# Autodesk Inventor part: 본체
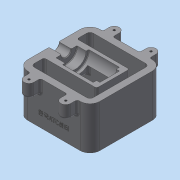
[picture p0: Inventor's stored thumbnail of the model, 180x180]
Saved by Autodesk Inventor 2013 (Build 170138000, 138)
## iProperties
Created: 2018-01
Part Number: 본체
Material: 일반
Document SubType Name: Modeling
Designer: dgall
Density: 1 g/cm^3
Author: dgall
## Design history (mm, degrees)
sketch "스케치1"
  geometry: L1 (0, 0)-(110, 0); L2 (110, 0)-(110, 110); L3 (110, 110)-(0, 110); L4 (0, 110)-(0, 0); L5 (10, 100)-(100, 100); L6 (100, 100)-(100, 10); L7 (100, 10)-(10, 10); L8 (10, 10)-(10, 100)
  constraints: 16 end point, 4 parallel, 2 perpendicular, 1 horizontal, 3 other
  dimensions: "d0" = 110 distance of L1.start L1.end; "d1" = 110 distance of L1.end L2.end; "d2" = 10 distance between parallel lines of L5 L3
extrude "돌출1" new body sketch "스케치1" distance "d3" = 65; taper "d4" = 0 deg
sketch "스케치2"
  geometry: L1 (110, 110)-(0, 110) reference; L2 (0, 110)-(0, 0) reference; L3 (19.5, 120)-(19.5, 110); L4 (34.5, 120)-(34.5, 110); L5 (75.5, 120)-(75.5, 110); L6 (90.5, 120)-(90.5, 110); A1 r 7.5 centre (27, 120) between (34.5, 120) and (19.5, 120); A2 r 7.5 centre (83, 120) between (90.5, 120) and (75.5, 120)
  constraints: 8 end point, 4 perpendicular, 4 point on circle, 4 point on line, 4 tangent, 2 centre point, 1 horizontal alignment
  dimensions: "d5" = 15 diameter of A1; "d6" = 15 diameter of A2; "d7" = 27 distance from line of A1.centre L2; "d8" = 56 distance of A2.centre A1.centre; "d9" = 10 distance from line of A1.centre L1
extrude "돌출2" join sketch "스케치2" distance "d10" = 20; taper "d11" = 0 deg
node "작업 평면1"
sketch "스케치3"
  geometry: A1 r 7.5 centre (27, -10) between (19.5, -10) and (34.5, -10) reference; A2 r 7.5 centre (83, -10) between (75.5, -10) and (90.5, -10) reference; A3 r 7.5 centre (83, 120) between (90.5, 120) and (75.5, 120) reference; A4 r 7.5 centre (27, 120) between (34.5, 120) and (19.5, 120) reference; 4 further points
  constraints: 4 coincident
hole "구멍1" sketch "스케치3" at (27, 120), (83, 120), (27, -10), (83, -10) diameter "d12" = 3.242; stored, may be unused: countersink angle "d16" = 90 deg, drill point angle "d18" = 118 deg; dims "d13" = 9, "d14" = 4, "d15" = 2, "d17" = 11
node "작업 평면2"
sketch "스케치5"
  geometry: L1 (0, 0)-(0, 65) reference; L2 (0, 65)-(10, 65) reference; L3 (10, 65)-(10, 0) reference; L4 (10, 0)-(0, 0) reference; L5 (110, 65)-(110, 0) reference; L6 (110, 0)-(100, 0) reference; L7 (100, 0)-(100, 65) reference; L8 (100, 65)-(110, 65) reference; L9 (90, 65)-(90, 30); L10 (90, 30)-(10, 8.564); L11 (10, 65)-(10, 8.564); L12 (10, 65)-(90, 65); L13 (100, 0)-(10, 0) reference
  constraints: 8 end point, 2 perpendicular, 1 parallel, 1 point on line
  dimensions: "d22" = 20 distance between parallel lines of L5 L9; "d23" = 105 deg angle of L3 L10; "d24" = 30 distance from line of L13 L9.end
extrude "돌출3" join sketch "스케치5" distance "d25" = 50; taper "d26" = 0 deg
sketch "스케치6"
  geometry: L1 (65, 110)-(65, 0) reference; C1 r 7.5 at (65, 55)
  constraints: 1 centre point, 1 midpoint
  dimensions: "d27" = 15 diameter of C1
extrude "돌출4" cut sketch "스케치6" distance "d28" = 19; taper "d29" = 0 deg
sketch "스케치7"
  geometry: C1 r 16 at (65, 55); A1 r 7.5 centre (65, 55) between (65, 62.5) and (65, 47.5) reference; 1 further point
  constraints: 1 centre point, 1 coincident
  dimensions: "d30" = 32 diameter of C1
extrude "돌출5" cut sketch "스케치7" distance "d31" = 14; taper "d32" = 0 deg
sketch "스케치8"
  geometry: C1 r 20 at (65, 55); A1 r 16 centre (65, 55) between (65, 71) and (65, 39) reference; 1 further point
  constraints: 1 centre point, 1 coincident
  dimensions: "d33" = 40 diameter of C1
extrude "돌출6" cut sketch "스케치8" distance "d34" = 47; taper "d35" = 0 deg
sketch "스케치9"
  geometry: C1 r 15 at (65, 55); A1 r 20 centre (65, 55) between (65, 75) and (65, 35) reference; 1 further point
  constraints: 1 centre point, 1 coincident
  dimensions: "d36" = 30 diameter of C1
extrude "돌출7" cut sketch "스케치9" distance "d37" = 5; taper "d38" = 0 deg
fillet "모깎기1" dims "d39" = 3
fillet "모깎기2" dims "d40" = 3
node "작업 평면3"
sketch "스케치10"
  geometry: L1 (100, 65)-(110, 65) reference; L2 (110, 65)-(110, 0) reference; L3 (110, 0)-(100, 0) reference; L4 (100, 0)-(100, 65) reference; L5 (90, 30)-(10, 8.564) reference; L6 (10, 8.564)-(10, 0) reference; L7 (10, 0)-(0, 0) reference; L8 (0, 0)-(0, 57.5) reference; L9 (0, 57.5)-(19, 57.5) reference; L10 (19, 57.5)-(19, 49) reference; L11 (19, 49)-(33, 49) reference; L12 (33, 49)-(33, 45) reference; L13 (33, 45)-(80, 45) reference; L14 (80, 45)-(80, 50) reference; L15 (80, 50)-(85, 50) reference; L16 (85, 50)-(85, 65) reference; L17 (85, 65)-(90, 65) reference; L18 (90, 65)-(90, 30) reference; L19 (38, 50)-(38, 39.243); L20 (38, 39.243)-(0, 29.061); L21 (38, 50)-(75, 50); L22 (75, 50)-(75, 31.157); L23 (75, 31.157)-(0, 11.061); L24 (100, 65)-(110, 65) reference; L25 (110, 65)-(110, 0) reference; L26 (110, 0)-(100, 0) reference; L27 (100, 0)-(100, 65) reference; L28 (90, 30)-(10, 8.564) reference; L29 (10, 8.564)-(10, 0) reference; L30 (10, 0)-(0, 0) reference; L31 (0, 0)-(0, 57.5) reference; L32 (0, 57.5)-(19, 57.5) reference; L33 (19, 57.5)-(19, 49) reference; L34 (19, 49)-(33, 49) reference; L35 (33, 49)-(33, 45) reference; L36 (33, 45)-(80, 45) reference; L37 (80, 45)-(80, 50) reference; L38 (80, 50)-(85, 50) reference; L39 (85, 50)-(85, 65) reference; L40 (85, 65)-(90, 65) reference; L41 (90, 65)-(90, 30) reference; L42 (33, 65)-(80, 65) reference; 2 further points
  constraints: 10 end point, 3 parallel, 2 midpoint, 2 perpendicular, 2 point on line, 1 vertical alignment
  dimensions: "d41" = 5 distance between parallel lines of L5 L23; "d42" = 37 distance between parallel lines of L22 L19; "d43" = 18 distance of L23.end L20.end; "d44" = 5 distance between parallel lines of L13 L21
extrude "돌출8" cut sketch "스케치10" stored distance "d45" = 30; taper "d46" = 0 deg
chamfer "모따기1" distance "d47" = 1; stored, may be unused: second distance "d48" = 2, angle "d49" = 45 deg
fillet "모깎기3" dims "d50" = 1
fillet "모깎기4" dims "d51" = 15
fillet "모깎기5" dims "d52" = 5
fillet "모깎기6" dims "d53" = 3
fillet "모깎기7" dims "d54" = 3
fillet "모깎기8" dims "d55" = 3
fillet "모깎기9" dims "d56" = 3
fillet "모깎기10" dims "d57" = 3
fillet "모깎기11" dims "d58" = 3
fillet "모깎기12" dims "d59" = 3
fillet "모깎기14" dims "d61" = 3
fillet "모깎기15" dims "d62" = 3
fillet "모깎기16" dims "d63" = 1
fillet "모깎기17" dims "d68" = 3
sketch "스케치12" dims "d0" = 110, "d1" = 110, "d2" = 10, "d5" = 15, "d6" = 15, "d7" = 27, "d8" = 56, "d9" = 10
  geometry: L1 (-22.5, -65)-(57.5, -65) reference; L2 (-37.5, 0)-(-37.5, -65) reference; 1 further point
  constraints: 1 other
  dimensions: "d69" = 20 distance from line of L1 point (17.5, -45); "d70" = 55 distance from line of L2 point (17.5, -45)
feature "엠보싱2" sketch "스케치12" dims "d5" = 15, "d6" = 15, "d7" = 27, "d8" = 56, "d9" = 10, "d71" = 0.5, "d72" = 0
node "솔리드1"
mirror "대칭1"
node "절단 모서리 투영1"
node "절단 모서리 투영2"
node "절단 모서리 투영3"
